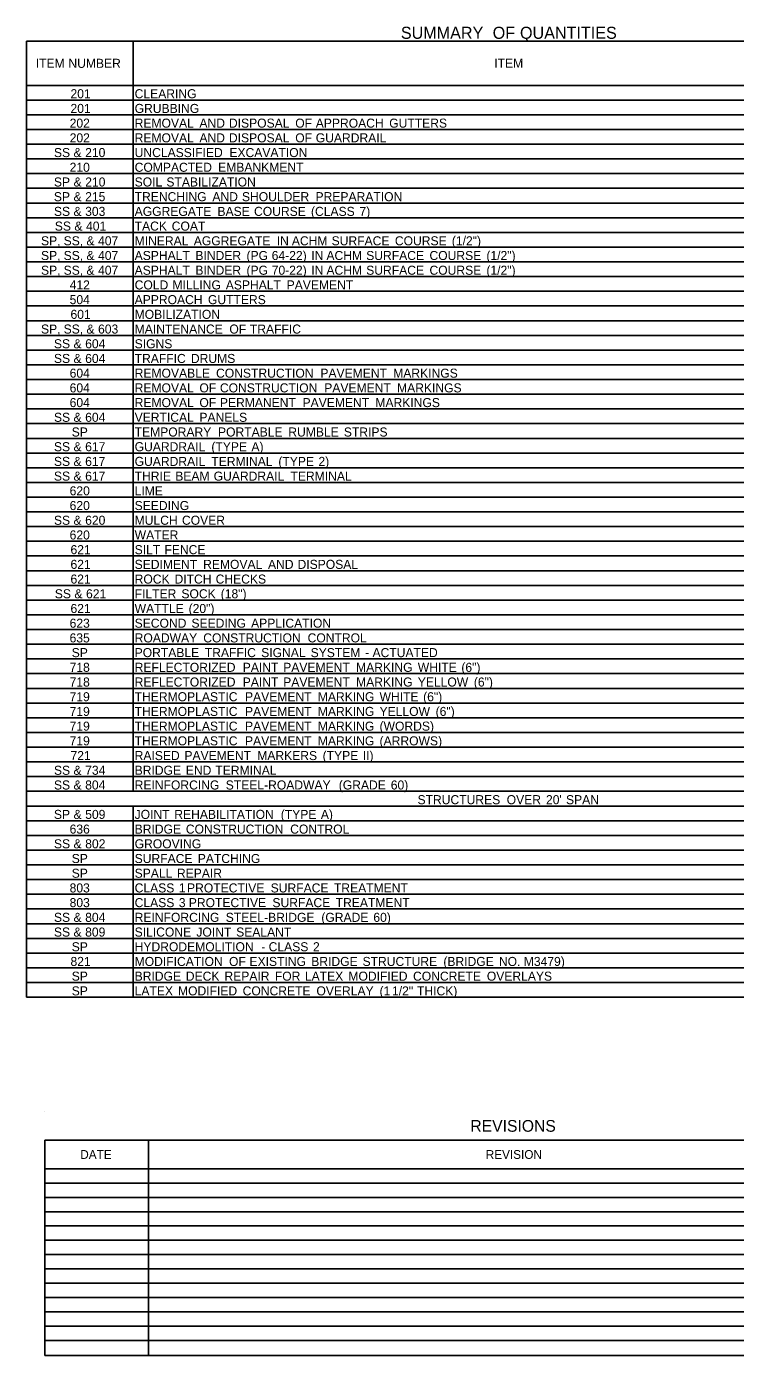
# Model space of a CAD drawing. Extents: x 542596 to 1930787, y -1948294 to 596640.
# Drawn here: x 544544 to 545014, y -1948211 to -1947330 of the extents above; entities that cross this region are included whole.
import ezdxf

# ---------------------------------------------------------------- set-up
doc = ezdxf.new("R2010")
doc.units = 0
doc.layers.add('Default', color=7, linetype='Continuous')

msp = doc.modelspace()

# ---------------------------------------------------------------- linework, layer by layer
at = {"layer": 'Default'}
for p, q in [((544543.96, -1947339.48), (544614.65, -1947339.48)), ((544543.96, -1947339.48), (545422.43, -1947339.48)), ((544543.96, -1947973.23), (544543.96, -1947339.48)), ((544543.96, -1947973.23), (544543.96, -1947339.48)), ((544614.65, -1947836.73), (544614.65, -1947339.48)), ((544543.96, -1947368.73), (545422.43, -1947368.73)), ((544614.65, -1947836.73), (544614.65, -1947368.73)), ((544543.96, -1947378.48), (545422.43, -1947378.48)), ((544543.96, -1947388.23), (545422.43, -1947388.23)), ((544543.96, -1947397.98), (545422.43, -1947397.98)), ((544543.96, -1947407.73), (545422.43, -1947407.73)), ((544543.96, -1947417.48), (545422.43, -1947417.48)), ((544543.96, -1947427.23), (545422.43, -1947427.23)), ((544543.96, -1947436.98), (545422.43, -1947436.98)), ((544543.96, -1947446.73), (545422.43, -1947446.73)), ((544543.96, -1947456.48), (545422.43, -1947456.48)), ((544543.96, -1947466.23), (545422.43, -1947466.23)), ((544543.96, -1947475.98), (545422.43, -1947475.98)), ((544543.96, -1947485.73), (545422.43, -1947485.73)), ((544543.96, -1947495.48), (545422.43, -1947495.48)), ((544543.96, -1947505.23), (545422.43, -1947505.23)), ((544543.96, -1947514.98), (545422.43, -1947514.98)), ((544543.96, -1947524.73), (545422.43, -1947524.73)), ((544543.96, -1947534.48), (545422.43, -1947534.48)), ((544543.96, -1947544.23), (545422.43, -1947544.23)), ((544543.96, -1947553.98), (545422.43, -1947553.98)), ((544543.96, -1947563.73), (545422.43, -1947563.73)), ((544543.96, -1947573.48), (545422.43, -1947573.48)), ((544543.96, -1947583.23), (545422.43, -1947583.23)), ((544543.96, -1947592.98), (545422.43, -1947592.98)), ((544543.96, -1947602.73), (545422.43, -1947602.73)), ((544543.96, -1947612.48), (545422.43, -1947612.48)), ((544543.96, -1947622.23), (545422.43, -1947622.23)), ((544543.96, -1947631.98), (545422.43, -1947631.98)), ((544543.96, -1947641.73), (545422.43, -1947641.73)), ((544543.96, -1947651.48), (545422.43, -1947651.48)), ((544543.96, -1947661.23), (545422.43, -1947661.23)), ((544543.96, -1947670.98), (545422.43, -1947670.98)), ((544543.96, -1947680.73), (545422.43, -1947680.73)), ((544543.96, -1947690.48), (545422.43, -1947690.48)), ((544543.96, -1947700.23), (545422.43, -1947700.23)), ((544543.96, -1947709.98), (545422.43, -1947709.98)), ((544543.96, -1947719.73), (545422.43, -1947719.73)), ((544543.96, -1947729.48), (545422.43, -1947729.48)), ((544543.96, -1947739.23), (545422.43, -1947739.23)), ((544543.96, -1947748.98), (545422.43, -1947748.98)), ((544543.96, -1947758.73), (545422.43, -1947758.73)), ((544543.96, -1947768.48), (545422.43, -1947768.48)), ((544543.96, -1947778.23), (545422.43, -1947778.23)), ((544543.96, -1947787.98), (545422.43, -1947787.98)), ((544543.96, -1947797.73), (545422.43, -1947797.73)), ((544543.96, -1947807.48), (545422.43, -1947807.48)), ((544543.96, -1947817.23), (545422.43, -1947817.23)), ((544543.96, -1947826.98), (545422.43, -1947826.98)), ((544543.96, -1947836.73), (545422.43, -1947836.73)), ((544543.96, -1947836.73), (545422.43, -1947836.73)), ((544543.96, -1947846.48), (545422.43, -1947846.48)), ((544543.96, -1947846.48), (545422.43, -1947846.48)), ((544614.65, -1947973.23), (544614.65, -1947846.48)), ((544614.65, -1947973.23), (544614.65, -1947846.48)), ((544543.96, -1947856.23), (545422.43, -1947856.23)), ((544543.96, -1947865.98), (545422.43, -1947865.98)), ((544543.96, -1947875.73), (545422.43, -1947875.73)), ((544543.96, -1947885.48), (545422.43, -1947885.48)), ((544543.96, -1947895.23), (545422.43, -1947895.23)), ((544543.96, -1947904.98), (545422.43, -1947904.98)), ((544543.96, -1947914.73), (545422.43, -1947914.73)), ((544543.96, -1947924.48), (545422.43, -1947924.48)), ((544543.96, -1947934.23), (545422.43, -1947934.23)), ((544543.96, -1947943.98), (545422.43, -1947943.98)), ((544543.96, -1947953.73), (545422.43, -1947953.73)), ((544543.96, -1947963.48), (545422.43, -1947963.48)), ((544543.96, -1947973.23), (545422.43, -1947973.23)), ((544556.08, -1948049.05), (544556.08, -1948049.05)), ((544556.08, -1948068.01), (545411.29, -1948068.01)), ((544556.08, -1948068.01), (544624.82, -1948068.01)), ((544556.08, -1948210.7), (544556.08, -1948068.01)), ((544624.82, -1948210.7), (544624.82, -1948068.01)), ((544556.08, -1948086.97), (545411.29, -1948086.97)), ((544556.08, -1948096.45), (545411.29, -1948096.45)), ((544556.08, -1948105.93), (545411.29, -1948105.93)), ((544556.08, -1948115.42), (545411.29, -1948115.42)), ((544556.08, -1948124.9), (545411.29, -1948124.9)), ((544556.08, -1948134.38), (545411.29, -1948134.38)), ((544556.08, -1948143.86), (545411.29, -1948143.86)), ((544556.08, -1948153.34), (545411.29, -1948153.34)), ((544556.08, -1948162.82), (545411.29, -1948162.82)), ((544556.08, -1948172.3), (545411.29, -1948172.3)), ((544556.08, -1948181.78), (545411.29, -1948181.78)), ((544556.08, -1948191.27), (545411.29, -1948191.27)), ((544556.08, -1948200.75), (545411.29, -1948200.75)), ((544556.08, -1948210.7), (545411.29, -1948210.7))]:
    msp.add_line(p, q, dxfattribs=at)

# ---------------------------------------------------------------- texts
for s, height, p in [(' SUMMARY', 8, (544789.14, -1947337.88)), (' OF', 8, (544850.02, -1947337.88)), (' QUANTITIES', 8, (544868.13, -1947337.88)), ('ITEM', 6, (544550.05, -1947357.11)), (' NUMBER', 6, (544569.47, -1947357.11)), ('ITEM', 6, (544854.04, -1947357.11)), ('201', 6, (544573.08, -1947377.28)), ('CLEARING', 6, (544615.62, -1947377.28)), ('201', 6, (544573.08, -1947387.03)), ('GRUBBING', 6, (544615.62, -1947387.03)), ('202', 6, (544572.53, -1947396.78)), ('REMOVAL', 6, (544615.62, -1947396.78)), (' AND', 6, (544656.32, -1947396.78)), (' DISPOSAL', 6, (544675.9, -1947396.78)), (' OF', 6, (544719.87, -1947396.78)), (' APPROACH', 6, (544733.46, -1947396.78)), (' GUTTERS', 6, (544782.17, -1947396.78)), ('202', 6, (544572.53, -1947406.53)), ('REMOVAL', 6, (544615.62, -1947406.53)), (' AND', 6, (544656.32, -1947406.53)), (' DISPOSAL', 6, (544675.9, -1947406.53)), (' OF', 6, (544719.87, -1947406.53)), (' GUARDRAIL', 6, (544733.46, -1947406.53)), ('SS', 6, (544562.11, -1947416.28)), (' &', 6, (544572.86, -1947416.28)), (' 210', 6, (544580.59, -1947416.28)), ('UNCLASSIFIED', 6, (544615.62, -1947416.28)), (' EXCAVATION', 6, (544676.2, -1947416.28)), ('210', 6, (544572.51, -1947426.03)), ('COMPACTED', 6, (544615.62, -1947426.03)), (' EMBANKMENT', 6, (544668.74, -1947426.03)), ('SP', 6, (544562.07, -1947435.78)), (' &', 6, (544572.89, -1947435.78)), (' 210', 6, (544580.62, -1947435.78)), ('SOIL', 6, (544615.62, -1947435.78)), (' STABILIZATION', 6, (544634.43, -1947435.78)), ('SP', 6, (544562.04, -1947445.53)), (' &', 6, (544572.86, -1947445.53)), (' 215', 6, (544580.59, -1947445.53)), ('TRENCHING', 6, (544615.62, -1947445.53)), (' AND', 6, (544664.93, -1947445.53)), (' SHOULDER', 6, (544684.52, -1947445.53)), (' PREPARATION', 6, (544733.32, -1947445.53)), ('SS', 6, (544562.1, -1947455.28)), (' &', 6, (544572.85, -1947455.28)), (' 303', 6, (544580.58, -1947455.28)), ('AGGREGATE', 6, (544615.62, -1947455.28)), (' BASE', 6, (544668.29, -1947455.28)), (' COURSE', 6, (544692.54, -1947455.28)), (' (CLASS', 6, (544730.29, -1947455.28)), (' 7)', 6, (544762.46, -1947455.28)), ('SS', 6, (544562.68, -1947465.03)), (' &', 6, (544573.43, -1947465.03)), (' 401', 6, (544581.16, -1947465.03)), ('TACK', 6, (544615.62, -1947465.03)), (' COAT', 6, (544637.96, -1947465.03)), ('SP,', 6, (544553.54, -1947474.78)), (' SS,', 6, (544566.31, -1947474.78)), (' &', 6, (544581.41, -1947474.78)), (' 407', 6, (544589.13, -1947474.78)), ('MINERAL', 6, (544615.62, -1947474.78)), (' AGGREGATE', 6, (544652.59, -1947474.78)), (' IN', 6, (544707.58, -1947474.78)), (' ACHM', 6, (544717.61, -1947474.78)), (' SURFACE', 6, (544743.99, -1947474.78)), (' COURSE', 6, (544785.93, -1947474.78)), (' (1/2")', 6, (544823.69, -1947474.78)), ('SP,', 6, (544553.54, -1947484.53)), (' SS,', 6, (544566.31, -1947484.53)), (' &', 6, (544581.41, -1947484.53)), (' 407', 6, (544589.13, -1947484.53)), ('ASPHALT', 6, (544615.62, -1947484.53)), (' BINDER', 6, (544653.66, -1947484.53)), (' (PG', 6, (544687.55, -1947484.53)), (' 64-22)', 6, (544704.26, -1947484.53)), (' IN', 6, (544730.5, -1947484.53)), (' ACHM', 6, (544740.53, -1947484.53)), (' SURFACE', 6, (544766.91, -1947484.53)), (' COURSE', 6, (544808.86, -1947484.53)), (' (1/2")', 6, (544846.61, -1947484.53)), ('SP,', 6, (544553.54, -1947494.28)), (' SS,', 6, (544566.31, -1947494.28)), (' &', 6, (544581.41, -1947494.28)), (' 407', 6, (544589.13, -1947494.28)), ('ASPHALT', 6, (544615.62, -1947494.28)), (' BINDER', 6, (544653.66, -1947494.28)), (' (PG', 6, (544687.55, -1947494.28)), (' 70-22)', 6, (544704.26, -1947494.28)), (' IN', 6, (544730.5, -1947494.28)), (' ACHM', 6, (544740.53, -1947494.28)), (' SURFACE', 6, (544766.91, -1947494.28)), (' COURSE', 6, (544808.86, -1947494.28)), (' (1/2")', 6, (544846.61, -1947494.28)), ('412', 6, (544572.53, -1947504.03)), ('COLD', 6, (544615.62, -1947504.03)), (' MILLING', 6, (544638.46, -1947504.03)), (' ASPHALT', 6, (544673.8, -1947504.03)), (' PAVEMENT', 6, (544714.17, -1947504.03)), ('504', 6, (544572.52, -1947513.78)), ('APPROACH', 6, (544615.62, -1947513.78)), (' GUTTERS', 6, (544662, -1947513.78)), ('601', 6, (544573.08, -1947523.53)), ('MOBILIZATION', 6, (544615.62, -1947523.53)), ('SP,', 6, (544553.54, -1947533.28)), (' SS,', 6, (544566.31, -1947533.28)), (' &', 6, (544581.41, -1947533.28)), (' 603', 6, (544589.13, -1947533.28)), ('MAINTENANCE', 6, (544615.62, -1947533.28)), (' OF', 6, (544676.2, -1947533.28)), (' TRAFFIC', 6, (544689.78, -1947533.28)), ('SS', 6, (544562.11, -1947543.03)), (' &', 6, (544572.86, -1947543.03)), (' 604', 6, (544580.59, -1947543.03)), ('SIGNS', 6, (544615.62, -1947543.03)), ('SS', 6, (544562.11, -1947552.78)), (' &', 6, (544572.86, -1947552.78)), (' 604', 6, (544580.59, -1947552.78)), ('TRAFFIC', 6, (544615.62, -1947552.78)), (' DRUMS', 6, (544650.68, -1947552.78)), ('604', 6, (544572.52, -1947562.53)), ('REMOVABLE', 6, (544615.62, -1947562.53)), (' CONSTRUCTION', 6, (544667.36, -1947562.53)), (' PAVEMENT', 6, (544736.54, -1947562.53)), (' MARKINGS', 6, (544784.82, -1947562.53)), ('604', 6, (544572.52, -1947572.28)), ('REMOVAL', 6, (544615.62, -1947572.28)), (' OF', 6, (544656.32, -1947572.28)), (' CONSTRUCTION', 6, (544669.91, -1947572.28)), (' PAVEMENT', 6, (544739.09, -1947572.28)), (' MARKINGS', 6, (544787.37, -1947572.28)), ('604', 6, (544572.52, -1947582.03)), ('REMOVAL', 6, (544615.62, -1947582.03)), (' OF', 6, (544656.32, -1947582.03)), (' PERMANENT', 6, (544669.91, -1947582.03)), (' PAVEMENT', 6, (544724.71, -1947582.03)), (' MARKINGS', 6, (544772.99, -1947582.03)), ('SS', 6, (544562.11, -1947591.78)), (' &', 6, (544572.86, -1947591.78)), (' 604', 6, (544580.59, -1947591.78)), ('VERTICAL', 6, (544615.62, -1947591.78)), (' PANELS', 6, (544656.32, -1947591.78)), ('SP', 6, (544573.89, -1947601.53)), ('TEMPORARY', 6, (544615.62, -1947601.53)), (' PORTABLE', 6, (544668.66, -1947601.53)), (' RUMBLE', 6, (544715.27, -1947601.53)), (' STRIPS', 6, (544752.09, -1947601.53)), ('SS', 6, (544562.1, -1947611.28)), (' &', 6, (544572.85, -1947611.28)), (' 617', 6, (544580.58, -1947611.28)), ('GUARDRAIL', 6, (544615.62, -1947611.28)), (' (TYPE', 6, (544664.24, -1947611.28)), (' A)', 6, (544690.81, -1947611.28)), ('SS', 6, (544562.1, -1947621.03)), (' &', 6, (544572.85, -1947621.03)), (' 617', 6, (544580.58, -1947621.03)), ('GUARDRAIL', 6, (544615.62, -1947621.03)), (' TERMINAL', 6, (544664.24, -1947621.03)), (' (TYPE', 6, (544708.66, -1947621.03)), (' 2)', 6, (544735.23, -1947621.03)), ('SS', 6, (544562.1, -1947630.78)), (' &', 6, (544572.85, -1947630.78)), (' 617', 6, (544580.58, -1947630.78)), ('THRIE', 6, (544615.62, -1947630.78)), (' BEAM', 6, (544640.32, -1947630.78)), (' GUARDRAIL', 6, (544665.78, -1947630.78)), (' TERMINAL', 6, (544716.73, -1947630.78)), ('620', 6, (544572.51, -1947640.53)), ('LIME', 6, (544615.62, -1947640.53)), ('620', 6, (544572.51, -1947650.28)), ('SEEDING', 6, (544615.62, -1947650.28)), ('SS', 6, (544562.11, -1947660.03)), (' &', 6, (544572.86, -1947660.03)), (' 620', 6, (544580.59, -1947660.03)), ('MULCH', 6, (544615.62, -1947660.03)), (' COVER', 6, (544644.75, -1947660.03)), ('620', 6, (544572.51, -1947669.78)), ('WATER', 6, (544615.62, -1947669.78)), ('621', 6, (544573.08, -1947679.53)), ('SILT', 6, (544615.62, -1947679.53)), (' FENCE', 6, (544633.15, -1947679.53)), ('621', 6, (544573.08, -1947689.28)), ('SEDIMENT', 6, (544615.62, -1947689.28)), (' REMOVAL', 6, (544658.77, -1947689.28)), (' AND', 6, (544701.8, -1947689.28)), (' DISPOSAL', 6, (544721.38, -1947689.28)), ('621', 6, (544573.08, -1947699.03)), ('ROCK', 6, (544615.62, -1947699.03)), (' DITCH', 6, (544639.83, -1947699.03)), (' CHECKS', 6, (544667.09, -1947699.03)), ('SS', 6, (544562.68, -1947708.78)), (' &', 6, (544573.43, -1947708.78)), (' 621', 6, (544581.16, -1947708.78)), ('FILTER', 6, (544615.62, -1947708.78)), (' SOCK', 6, (544644.39, -1947708.78)), (' (18")', 6, (544670.46, -1947708.78)), ('621', 6, (544573.08, -1947718.53)), ('WATTLE', 6, (544615.62, -1947718.53)), (' (20")', 6, (544649.17, -1947718.53)), ('623', 6, (544572.5, -1947728.28)), ('SECOND', 6, (544615.62, -1947728.28)), (' SEEDING', 6, (544651.04, -1947728.28)), (' APPLICATION', 6, (544690.58, -1947728.28)), ('635', 6, (544572.48, -1947738.03)), ('ROADWAY', 6, (544615.62, -1947738.03)), (' CONSTRUCTION', 6, (544658.88, -1947738.03)), (' CONTROL', 6, (544728.06, -1947738.03)), ('SP', 6, (544573.89, -1947747.78)), ('PORTABLE', 6, (544615.62, -1947747.78)), (' TRAFFIC', 6, (544659.9, -1947747.78)), (' SIGNAL', 6, (544697.29, -1947747.78)), (' SYSTEM', 6, (544730.07, -1947747.78)), (' ACTUATED', 6, (544771.1, -1947747.78)), ('718', 6, (544572.5, -1947757.53)), ('REFLECTORIZED', 6, (544615.62, -1947757.53)), (' PAINT', 6, (544685.05, -1947757.53)), (' PAVEMENT', 6, (544711.89, -1947757.53)), (' MARKING', 6, (544760.18, -1947757.53)), (' -', 6, (544766.25, -1947747.78)), (' WHITE', 6, (544801.11, -1947757.53)), (' (6")', 6, (544830, -1947757.53)), ('718', 6, (544572.5, -1947767.28)), ('REFLECTORIZED', 6, (544615.62, -1947767.28)), (' PAINT', 6, (544685.05, -1947767.28)), (' PAVEMENT', 6, (544711.89, -1947767.28)), (' MARKING', 6, (544760.18, -1947767.28)), (' YELLOW', 6, (544801.11, -1947767.28)), (' (6")', 6, (544838.28, -1947767.28)), ('719', 6, (544572.5, -1947777.03)), ('THERMOPLASTIC', 6, (544615.62, -1947777.03)), (' PAVEMENT', 6, (544686.56, -1947777.03)), (' MARKING', 6, (544734.84, -1947777.03)), (' WHITE', 6, (544775.77, -1947777.03)), (' (6")', 6, (544804.66, -1947777.03)), ('719', 6, (544572.5, -1947786.78)), ('THERMOPLASTIC', 6, (544615.62, -1947786.78)), (' PAVEMENT', 6, (544686.56, -1947786.78)), (' MARKING', 6, (544734.84, -1947786.78)), (' YELLOW', 6, (544775.77, -1947786.78)), (' (6")', 6, (544812.94, -1947786.78)), ('719', 6, (544572.5, -1947796.53)), ('THERMOPLASTIC', 6, (544615.62, -1947796.53)), (' PAVEMENT', 6, (544686.56, -1947796.53)), (' MARKING', 6, (544734.84, -1947796.53)), (' (WORDS)', 6, (544775.77, -1947796.53)), ('719', 6, (544572.5, -1947806.28)), ('THERMOPLASTIC', 6, (544615.62, -1947806.28)), (' PAVEMENT', 6, (544686.56, -1947806.28)), (' MARKING', 6, (544734.84, -1947806.28)), (' (ARROWS)', 6, (544775.77, -1947806.28)), ('721', 6, (544573.08, -1947816.03)), ('RAISED', 6, (544615.62, -1947816.03)), (' PAVEMENT', 6, (544646.39, -1947816.03)), (' MARKERS', 6, (544694.67, -1947816.03)), (' (TYPE', 6, (544738.03, -1947816.03)), (' II)', 6, (544764.6, -1947816.03)), ('SS', 6, (544562.11, -1947825.78)), (' &', 6, (544572.86, -1947825.78)), (' 734', 6, (544580.59, -1947825.78)), ('BRIDGE', 6, (544615.62, -1947825.78)), (' END', 6, (544647.32, -1947825.78)), (' TERMINAL', 6, (544666.9, -1947825.78)), ('SS', 6, (544562.11, -1947835.53)), (' &', 6, (544572.86, -1947835.53)), (' 804', 6, (544580.59, -1947835.53)), ('REINFORCING', 6, (544615.62, -1947835.53)), (' STEEL-ROADWAY', 6, (544673.78, -1947835.53)), (' (GRADE', 6, (544748.72, -1947835.53)), (' 60)', 6, (544783.2, -1947835.53)), ('STRUCTURES', 6, (544803.18, -1947845.28)), (' OVER', 6, (544860.06, -1947845.28)), (" 20'", 6, (544886.11, -1947845.28)), (' SPAN', 6, (544899.39, -1947845.28)), ('SP', 6, (544562.06, -1947855.03)), (' &', 6, (544572.88, -1947855.03)), (' 509', 6, (544580.61, -1947855.03)), ('JOINT', 6, (544615.62, -1947855.03)), (' REHABILITATION', 6, (544639.67, -1947855.03)), (' (TYPE', 6, (544710.26, -1947855.03)), (' A)', 6, (544736.83, -1947855.03)), ('636', 6, (544572.5, -1947864.78)), ('BRIDGE', 6, (544615.62, -1947864.78)), (' CONSTRUCTION', 6, (544647.32, -1947864.78)), (' CONTROL', 6, (544716.5, -1947864.78)), ('SS', 6, (544562.13, -1947874.53)), (' &', 6, (544572.88, -1947874.53)), (' 802', 6, (544580.61, -1947874.53)), ('GROOVING', 6, (544615.62, -1947874.53)), ('SP', 6, (544573.89, -1947884.28)), ('SURFACE', 6, (544615.62, -1947884.28)), (' PATCHING', 6, (544655.24, -1947884.28)), ('SP', 6, (544573.89, -1947894.03)), ('SPALL', 6, (544615.62, -1947894.03)), (' REPAIR', 6, (544641.42, -1947894.03)), ('803', 6, (544572.5, -1947903.78)), ('CLASS', 6, (544615.62, -1947903.78)), (' 1', 6, (544642.68, -1947903.78)), (' PROTECTIVE', 6, (544648.12, -1947903.78)), (' SURFACE', 6, (544703.58, -1947903.78)), (' TREATMENT', 6, (544745.52, -1947903.78)), ('803', 6, (544572.5, -1947913.53)), ('CLASS', 6, (544615.62, -1947913.53)), (' 3', 6, (544642.68, -1947913.53)), (' PROTECTIVE', 6, (544649.28, -1947913.53)), (' SURFACE', 6, (544704.74, -1947913.53)), (' TREATMENT', 6, (544746.68, -1947913.53)), ('SS', 6, (544562.11, -1947923.28)), (' &', 6, (544572.86, -1947923.28)), (' 804', 6, (544580.59, -1947923.28)), ('REINFORCING', 6, (544615.62, -1947923.28)), (' STEEL-BRIDGE', 6, (544673.78, -1947923.28)), (' (GRADE', 6, (544737.16, -1947923.28)), (' 60)', 6, (544771.64, -1947923.28)), ('SS', 6, (544562.1, -1947933.03)), (' &', 6, (544572.84, -1947933.03)), (' 809', 6, (544580.57, -1947933.03)), ('SILICONE', 6, (544615.62, -1947933.03)), (' JOINT', 6, (544654.3, -1947933.03)), (' SEALANT', 6, (544680.68, -1947933.03)), ('SP', 6, (544573.89, -1947942.78)), ('HYDRODEMOLITION', 6, (544615.62, -1947942.78)), (' CLASS', 6, (544702.24, -1947942.78)), (' 2', 6, (544731.62, -1947942.78)), ('821', 6, (544573.08, -1947952.53)), ('MODIFICATION', 6, (544615.62, -1947952.53)), (' OF', 6, (544675.95, -1947952.53)), (' EXISTING', 6, (544689.53, -1947952.53)), (' -', 6, (544697.38, -1947942.78)), (' BRIDGE', 6, (544730.47, -1947952.53)), (' STRUCTURE', 6, (544764.49, -1947952.53)), (' (BRIDGE', 6, (544818.07, -1947952.53)), (' NO.', 6, (544854.89, -1947952.53)), (' M3479)', 6, (544871.39, -1947952.53)), ('SP', 6, (544573.89, -1947962.28)), ('BRIDGE', 6, (544615.62, -1947962.28)), (' DECK', 6, (544647.32, -1947962.28)), (' REPAIR', 6, (544672.92, -1947962.28)), (' FOR', 6, (544706.35, -1947962.28)), (' LATEX', 6, (544726.26, -1947962.28)), (' MODIFIED', 6, (544755.1, -1947962.28)), (' CONCRETE', 6, (544797.96, -1947962.28)), (' OVERLAYS', 6, (544846.89, -1947962.28)), ('SP', 6, (544573.89, -1947972.03)), ('LATEX', 6, (544615.62, -1947972.03)), (' MODIFIED', 6, (544642.13, -1947972.03)), (' CONCRETE', 6, (544684.99, -1947972.03)), (' OVERLAY', 6, (544733.92, -1947972.03)), (' (1', 6, (544775.79, -1947972.03)), (' 1/2"', 6, (544784.03, -1947972.03)), (' THICK)', 6, (544800.59, -1947972.03)), ('REVISIONS', 7.78, (544838.2, -1948062.42)), ('DATE', 5.835, (544579.55, -1948080.41)), ('REVISION', 5.835, (544848.38, -1948080.41))]:
    msp.add_text(s, height=height, dxfattribs=at).set_placement(p)

doc.saveas('drawing.dxf')
